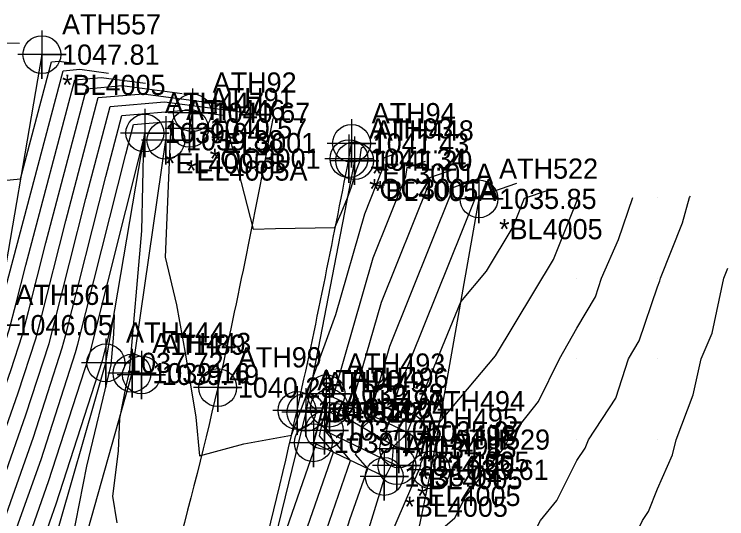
# Model space of a CAD drawing. Extents: x 1213164 to 1213550, y 766120 to 766870.
# Drawn here: x 1213390.3 to 1213478.6, y 766780.2 to 766842.7 of the extents above; entities that cross this region are included whole.
import ezdxf

# ---------------------------------------------------------------- set-up
doc = ezdxf.new("R2010")
doc.units = 0
for name, color, linetype in [('Default', 7, 'Continuous'), ('Exist DTM Breakline', 7, 'Continuous'), ('Exist DTM Breakline Cogo Comment', 7, 'Continuous'), ('Exist DTM Breakline Cogo Elevation', 7, 'Continuous'), ('Exist DTM Breakline Cogo Number', 7, 'Continuous'), ('Exist DTM Breakline Cogo Point CELL', 7, 'Continuous'), ('Exist DTM Crownline', 7, 'Continuous'), ('Exist DTM Crownline Cogo Elevation', 7, 'Continuous'), ('Exist DTM Crownline Cogo Number', 7, 'Continuous'), ('Exist DTM Crownline Cogo Point CELL', 7, 'Continuous'), ('Exist DTM QL2 LIDAR Elevation Point', 7, 'Continuous'), ('Exist Roads EOP', 7, 'Continuous'), ('Exist Roads EOP Cogo Comment', 7, 'Continuous'), ('Exist Roads EOP Cogo Elevation', 7, 'Continuous'), ('Exist Roads EOP Cogo Number', 7, 'Continuous'), ('Exist Roads EOP Cogo Point CELL', 7, 'Continuous')]:
    doc.layers.add(name, color=color, linetype=linetype)

msp = doc.modelspace()

# ---------------------------------------------------------------- linework, layer by layer
at = {"layer": 'Default'}
for points in [[(1213340, 766783.914), (1213346.197, 766783.803), (1213350, 766788.887), (1213350.252, 766789.748), (1213350.345, 766790), (1213352.211, 766797.789), (1213353.788, 766800), (1213355.691, 766804.309), (1213359.889, 766810), (1213359.934, 766810.066), (1213360, 766810.135), (1213363.986, 766816.014), (1213366.89, 766820), (1213368.115, 766821.885), (1213370, 766824.609), (1213372.455, 766827.545), (1213374.385, 766830), (1213376.747, 766833.253), (1213380, 766838.01), (1213384.981, 766839.17), (1213390.964, 766839.142)], [(1213342.135, 766770), (1213344.532, 766775.468), (1213350, 766775.398), (1213353.024, 766776.976), (1213354.408, 766780), (1213355.675, 766784.325), (1213357.755, 766790), (1213358.189, 766791.811), (1213360, 766794.351), (1213362.493, 766797.507), (1213363.789, 766800), (1213366.059, 766803.941), (1213370, 766809.883), (1213370.043, 766809.957), (1213370.062, 766810), (1213373.648, 766816.352), (1213379.123, 766820), (1213379.522, 766820.478), (1213380, 766821.085), (1213381.062, 766821.371), (1213391.073, 766822.338), (1213394.898, 766836.818), (1213395.832, 766836.898), (1213397.407, 766836.692)], [(1213389.27, 766808.897), (1213396.353, 766835.709), (1213398.446, 766835.888), (1213401.976, 766835.427)], [(1213342.06, 766740), (1213346.924, 766743.076), (1213350, 766747.184), (1213351.299, 766748.701), (1213352.342, 766750), (1213356.02, 766753.98), (1213360, 766758.382), (1213361.077, 766760), (1213363.847, 766766.153), (1213367.746, 766770), (1213368.826, 766771.174), (1213370, 766773.592), (1213377.267, 766776.571), (1213378.809, 766776.986), (1213379.962, 766782.672), (1213380.675, 766777.94), (1213388.927, 766801.313), (1213389.67, 766803.609), (1213390.551, 766806.911), (1213391.743, 766811.64), (1213397.808, 766834.6), (1213401.06, 766834.878), (1213406.544, 766834.161)], [(1213342.106, 766727.894), (1213344.486, 766730), (1213347.806, 766732.194), (1213350, 766733.538), (1213354.074, 766735.926), (1213358.171, 766740), (1213359.015, 766740.985), (1213360, 766742.211), (1213370.384, 766750.082), (1213371.539, 766754.871), (1213373.745, 766752.907), (1213380.812, 766772.675), (1213381.861, 766775.895), (1213389.865, 766798.563), (1213391.317, 766803.048), (1213392.077, 766805.896), (1213394.215, 766814.384), (1213399.263, 766833.491), (1213403.674, 766833.869), (1213411.113, 766832.895)], [(1213340, 766710.039), (1213345.861, 766714.139), (1213350, 766719.109), (1213350.563, 766720), (1213354.645, 766725.355), (1213360, 766728.235), (1213361.865, 766727.151), (1213367.981, 766729.516), (1213374.34, 766749.027), (1213374.823, 766750.271), (1213381.781, 766769.733), (1213384.002, 766776.552), (1213390.803, 766795.813), (1213392.964, 766802.487), (1213393.602, 766804.881), (1213396.688, 766817.128), (1213400.718, 766832.382), (1213406.288, 766832.859), (1213415.682, 766831.63)], [(1213342.112, 766697.888), (1213348.381, 766700), (1213349.604, 766700.396), (1213350, 766700.737), (1213351.462, 766701.499), (1213361.797, 766706.63), (1213364.872, 766714.303), (1213364.991, 766714.639), (1213366.766, 766720.251), (1213367.777, 766722.939), (1213375.885, 766747.814), (1213376.911, 766750.459), (1213382.75, 766766.792), (1213386.143, 766777.209), (1213391.741, 766793.063), (1213394.611, 766801.925), (1213395.128, 766803.866), (1213399.161, 766819.872), (1213402.173, 766831.273), (1213408.902, 766831.849), (1213420.25, 766830.364)], [(1213370.731, 766726.053), (1213377.429, 766746.602), (1213378.998, 766750.648), (1213383.718, 766763.851), (1213388.284, 766777.866), (1213392.679, 766790.313), (1213396.257, 766801.364), (1213396.654, 766802.85), (1213401.634, 766822.616), (1213403.628, 766830.164), (1213411.517, 766830.839), (1213416.18, 766830.229), (1213416.57, 766829.106), (1213419.898, 766816.103), (1213422.656, 766816.169), (1213430.019, 766816.293), (1213430.817, 766818.052), (1213431.586, 766819.952), (1213432.084, 766821.325), (1213432.692, 766823.445), (1213433.07, 766824.384), (1213433.314, 766826.182), (1213433.718, 766826.322)], [(1213390.425, 766778.523), (1213393.617, 766787.563), (1213397.904, 766800.803), (1213398.18, 766801.835), (1213404.107, 766825.36), (1213405.083, 766829.055), (1213409.963, 766829.473), (1213409.602, 766827.626), (1213409.606, 766827.357), (1213408.987, 766812.605), (1213410.391, 766806.703), (1213411.541, 766800.502), (1213412.783, 766792.805), (1213413.261, 766788.017), (1213418.736, 766789.503), (1213424.652, 766790.556), (1213425.762, 766793.537), (1213426.086, 766794.404), (1213427.001, 766796.892), (1213427.227, 766797.449), (1213430.151, 766805.518), (1213433.726, 766817.979), (1213435.948, 766823.5), (1213436.145, 766824.949), (1213437.487, 766825.415)], [(1213392.566, 766779.181), (1213394.555, 766784.814), (1213399.551, 766800.241), (1213399.705, 766800.82), (1213406.328, 766827.105), (1213406.06, 766815.865), (1213404.533, 766798.386), (1213404.112, 766796.627), (1213403.326, 766792.643), (1213403.173, 766788.574), (1213402.481, 766783.012), (1213403.013, 766779.716)], [(1213423.086, 766776.13), (1213427.725, 766789.446), (1213427.474, 766789.739), (1213427.524, 766789.959), (1213429.015, 766795.399), (1213429.815, 766795.277), (1213434.76, 766812.513), (1213438.827, 766822.617), (1213438.976, 766823.716), (1213441.257, 766824.509)], [(1213407.121, 766726.367), (1213412.78, 766738.536), (1213414.717, 766743.514), (1213414.943, 766744.295), (1213420.982, 766762.391), (1213421.345, 766763.374), (1213423.08, 766769), (1213429.851, 766788.437), (1213428.115, 766790.46), (1213428.46, 766791.982), (1213429.189, 766794.641), (1213432.107, 766794.195), (1213435.794, 766807.048), (1213441.705, 766821.733), (1213441.807, 766822.483), (1213445.026, 766823.602)], [(1213406.915, 766715.546), (1213416.344, 766739.776), (1213417.797, 766744.803), (1213422.929, 766760.184), (1213423.719, 766762.321), (1213427.493, 766774.555), (1213431.978, 766787.427), (1213428.893, 766791.02), (1213428.912, 766791.058), (1213428.916, 766791.101), (1213429.527, 766793.815), (1213429.566, 766793.852), (1213434.398, 766793.113), (1213436.828, 766801.582), (1213444.584, 766820.849), (1213444.638, 766821.25), (1213448.796, 766822.695)], [(1213417.971, 766736.038), (1213420.651, 766745.31), (1213424.877, 766757.976), (1213426.094, 766761.269), (1213431.906, 766780.109), (1213434.104, 766786.417), (1213432.592, 766788.178), (1213433.028, 766789.06), (1213433.113, 766790.061), (1213433.44, 766791.514), (1213434.358, 766792.388), (1213436.689, 766792.031), (1213437.861, 766796.117), (1213447.462, 766819.966), (1213447.469, 766820.017), (1213452.565, 766821.788)], [(1213419.598, 766732.3), (1213423.505, 766745.817), (1213426.825, 766755.768), (1213428.468, 766760.216), (1213436.144, 766785.095), (1213436.305, 766785.469), (1213436.491, 766785.74), (1213437.143, 766787.062), (1213437.31, 766789.021), (1213437.353, 766789.213), (1213438.554, 766790.355), (1213439.045, 766790.985), (1213445.628, 766807.084), (1213448.839, 766810.887), (1213452.142, 766816.379), (1213453.546, 766819.913), (1213456.335, 766820.882)], [(1213421.225, 766728.562), (1213426.358, 766746.325), (1213428.773, 766753.561), (1213430.843, 766759.163), (1213436.058, 766776.068), (1213440.351, 766786.037), (1213440.617, 766786.424), (1213440.676, 766787.084), (1213442.087, 766790.175), (1213442.282, 766790.426), (1213442.981, 766792.135), (1213449.958, 766800.396), (1213457.134, 766812.327), (1213460, 766819.541), (1213460.14, 766819.86), (1213460.187, 766820)], [(1213422.851, 766724.824), (1213429.212, 766746.832), (1213430.721, 766751.353), (1213433.217, 766758.11), (1213435.973, 766767.041), (1213439.81, 766775.952), (1213444.889, 766780.311), (1213446.229, 766782.929), (1213450, 766787.756), (1213451.006, 766788.994), (1213451.51, 766790), (1213455.256, 766794.744), (1213457.857, 766800), (1213460, 766803.813), (1213462.314, 766807.686), (1213463.093, 766810), (1213465.195, 766814.805), (1213466.976, 766820)], [(1213424.478, 766721.086), (1213432.066, 766747.34), (1213432.669, 766749.145), (1213435.592, 766757.057), (1213435.887, 766758.014), (1213436.299, 766758.97), (1213449.746, 766770.512), (1213450, 766771.007), (1213453.629, 766776.371), (1213455.504, 766780), (1213457.52, 766782.48), (1213460, 766787.434), (1213461.032, 766788.968), (1213461.443, 766790), (1213464.863, 766795.137), (1213466.403, 766800), (1213467.748, 766802.252), (1213470, 766808.933), (1213470.32, 766809.68), (1213470.389, 766810), (1213473.119, 766816.881), (1213473.967, 766820), (1213474.094, 766820.154)], [(1213432.563, 766724.347), (1213436.581, 766740.012), (1213437.508, 766743.17), (1213440, 766741.826), (1213445.936, 766744.064), (1213447.428, 766750), (1213450, 766755.519), (1213452.593, 766757.407), (1213455.201, 766760), (1213457.761, 766762.239), (1213460, 766766.007), (1213461.662, 766768.338), (1213462.651, 766770), (1213465.513, 766774.487), (1213468.136, 766780), (1213468.886, 766781.114), (1213470, 766783.912), (1213471.886, 766788.114), (1213472.323, 766790), (1213474.452, 766795.548), (1213475.417, 766800), (1213476.793, 766803.207), (1213478.245, 766810), (1213478.744, 766811.256)], [(1213379.596, 766735.396), (1213382.063, 766742.965), (1213385.261, 766751.214), (1213386.624, 766755.027), (1213394.707, 766779.838), (1213395.493, 766782.064), (1213401.198, 766799.68), (1213401.231, 766799.805), (1213402.663, 766805.491), (1213402.605, 766803.059), (1213402.275, 766799.279), (1213399.269, 766786.732), (1213397.9, 766779.789), (1213393.663, 766758.303), (1213393.59, 766756.355), (1213393.67, 766750.16), (1213393.673, 766750.105), (1213393.681, 766750.051), (1213394.967, 766742.851), (1213396.502, 766727.724)]]:
    msp.add_lwpolyline(points, dxfattribs=at)
at = {"layer": 'Exist DTM Breakline'}
for points in [[(1213393.725, 766837.712), (1213387.943, 766804.198), (1213372.969, 766750.103), (1213364.408, 766714.77), (1213354.911, 766685.163), (1213342.452, 766644.741), (1213315.98, 766668.508), (1213286.511, 766700.007), (1213270.126, 766717.647)], [(1213346.628, 766614.521), (1213356.147, 766642.326), (1213365.891, 766675.979), (1213376.506, 766712.04), (1213387.804, 766751.444), (1213401.652, 766799.525), (1213406.478, 766827.991)], [(1213348.967, 766613.21), (1213359.36, 766641.078), (1213368.166, 766674.744), (1213379.292, 766710.798), (1213391.46, 766750.473), (1213404.901, 766798.24), (1213409.089, 766827.096)], [(1213432.48, 766824.565), (1213426.442, 766793.398), (1213414.418, 766744.202), (1213402.864, 766704.233), (1213391.111, 766668.435), (1213399.916, 766666.943)], [(1213447.885, 766819.836), (1213441.941, 766786.26), (1213433.964, 766747.677), (1213424.337, 766715.269), (1213411.9, 766681.742)], [(1213436.147, 766785.447), (1213427.366, 766789.617), (1213428.949, 766795.686), (1213438.825, 766791.023)], [(1213437.948, 766788.863), (1213429.355, 766793.916), (1213428.727, 766791.148), (1213437.715, 766786.784)]]:
    msp.add_lwpolyline(points, dxfattribs=at)
at = {"layer": 'Exist DTM Breakline Cogo Point CELL'}
for points in [[(1213393.725, 766840.712), (1213393.725, 766834.712), (1213393.725, 766837.712), (1213396.725, 766837.712), (1213390.725, 766837.712)], [(1213406.478, 766830.991), (1213406.478, 766824.991), (1213406.478, 766827.991), (1213409.478, 766827.991), (1213403.478, 766827.991)], [(1213409.089, 766830.096), (1213409.089, 766824.096), (1213409.089, 766827.096), (1213412.089, 766827.096), (1213406.089, 766827.096)], [(1213432.48, 766827.565), (1213432.48, 766821.565), (1213432.48, 766824.565), (1213435.48, 766824.565), (1213429.48, 766824.565)], [(1213447.885, 766822.836), (1213447.885, 766816.836), (1213447.885, 766819.836), (1213450.885, 766819.836), (1213444.885, 766819.836)], [(1213387.943, 766807.198), (1213387.943, 766801.198), (1213387.943, 766804.198), (1213390.943, 766804.198), (1213384.943, 766804.198)], [(1213401.652, 766802.525), (1213401.652, 766796.525), (1213401.652, 766799.525), (1213404.652, 766799.525), (1213398.652, 766799.525)], [(1213404.901, 766801.24), (1213404.901, 766795.24), (1213404.901, 766798.24), (1213407.901, 766798.24), (1213401.901, 766798.24)], [(1213428.949, 766798.686), (1213428.949, 766792.686), (1213428.949, 766795.686), (1213431.949, 766795.686), (1213425.949, 766795.686)], [(1213429.355, 766796.916), (1213429.355, 766790.916), (1213429.355, 766793.916), (1213432.355, 766793.916), (1213426.355, 766793.916)], [(1213426.442, 766796.398), (1213426.442, 766790.398), (1213426.442, 766793.398), (1213429.442, 766793.398), (1213423.442, 766793.398)], [(1213428.727, 766794.148), (1213428.727, 766788.148), (1213428.727, 766791.148), (1213431.727, 766791.148), (1213425.727, 766791.148)], [(1213438.825, 766794.023), (1213438.825, 766788.023), (1213438.825, 766791.023), (1213441.825, 766791.023), (1213435.825, 766791.023)], [(1213427.366, 766792.617), (1213427.366, 766786.617), (1213427.366, 766789.617), (1213430.366, 766789.617), (1213424.366, 766789.617)], [(1213437.948, 766791.863), (1213437.948, 766785.863), (1213437.948, 766788.863), (1213440.948, 766788.863), (1213434.948, 766788.863)], [(1213437.715, 766789.784), (1213437.715, 766783.784), (1213437.715, 766786.784), (1213440.715, 766786.784), (1213434.715, 766786.784)], [(1213441.941, 766789.26), (1213441.941, 766783.26), (1213441.941, 766786.26), (1213444.941, 766786.26), (1213438.941, 766786.26)], [(1213436.147, 766788.447), (1213436.147, 766782.447), (1213436.147, 766785.447), (1213439.147, 766785.447), (1213433.147, 766785.447)]]:
    msp.add_lwpolyline(points, dxfattribs=at)
for centre in [(1213393.725, 766837.712), (1213406.478, 766827.991), (1213409.089, 766827.096), (1213432.48, 766824.565), (1213447.885, 766819.836), (1213401.652, 766799.525), (1213404.901, 766798.24), (1213428.949, 766795.686), (1213429.355, 766793.916), (1213426.442, 766793.398), (1213428.727, 766791.148), (1213438.825, 766791.023), (1213427.366, 766789.617), (1213437.948, 766788.863), (1213437.715, 766786.784), (1213441.941, 766786.26), (1213436.147, 766785.447)]:
    msp.add_circle(centre, 2.344, dxfattribs=at)
at = {"layer": 'Exist DTM Crownline'}
msp.add_spline([(1213422.346, 766829.784), (1213415.509, 766796.457), (1213402.624, 766748.087)], degree=3, dxfattribs=at)
at = {"layer": 'Exist DTM Crownline Cogo Point CELL'}
msp.add_lwpolyline([(1213415.509, 766799.457), (1213415.509, 766793.457), (1213415.509, 766796.457), (1213418.509, 766796.457), (1213412.509, 766796.457)], dxfattribs=at)
msp.add_circle((1213415.509, 766796.457), 2.344, dxfattribs=at)
at = {"layer": 'Exist DTM QL2 LIDAR Elevation Point'}
for p, q in [((1213460, 766820), (1213460, 766820)), ((1213470, 766820), (1213470, 766820)), ((1213460, 766810), (1213460, 766810)), ((1213470, 766810), (1213470, 766810)), ((1213450, 766800), (1213450, 766800)), ((1213460, 766800), (1213460, 766800)), ((1213470, 766800), (1213470, 766800)), ((1213450, 766790), (1213450, 766790)), ((1213460, 766790), (1213460, 766790)), ((1213470, 766790), (1213470, 766790))]:
    msp.add_line(p, q, dxfattribs=at)
at = {"layer": 'Exist Roads EOP'}
for p, q in [((1213412.014, 766828.572), (1213412.387, 766830.503)), ((1213431.775, 766824.817), (1213432.097, 766826.712))]:
    msp.add_line(p, q, dxfattribs=at)
msp.add_spline([(1213390.233, 766668.75), (1213399.517, 766704.888), (1213412.301, 766744.745), (1213425.35, 766793.621), (1213431.775, 766824.817)], degree=3, dxfattribs=at)
at = {"layer": 'Exist Roads EOP Cogo Point CELL'}
for points in [[(1213412.387, 766833.503), (1213412.387, 766827.503), (1213412.387, 766830.503), (1213415.387, 766830.503), (1213409.387, 766830.503)], [(1213412.014, 766831.572), (1213412.014, 766825.572), (1213412.014, 766828.572), (1213415.014, 766828.572), (1213409.014, 766828.572)], [(1213432.097, 766829.712), (1213432.097, 766823.712), (1213432.097, 766826.712), (1213435.097, 766826.712), (1213429.097, 766826.712)], [(1213431.775, 766827.817), (1213431.775, 766821.817), (1213431.775, 766824.817), (1213434.775, 766824.817), (1213428.775, 766824.817)], [(1213406.061, 766801.028), (1213406.061, 766795.028), (1213406.061, 766798.028), (1213409.061, 766798.028), (1213403.061, 766798.028)], [(1213425.35, 766796.621), (1213425.35, 766790.621), (1213425.35, 766793.621), (1213428.35, 766793.621), (1213422.35, 766793.621)]]:
    msp.add_lwpolyline(points, dxfattribs=at)
for centre in [(1213412.387, 766830.503), (1213412.014, 766828.572), (1213432.097, 766826.712), (1213431.775, 766824.817), (1213406.061, 766798.028), (1213425.35, 766793.621)]:
    msp.add_circle(centre, 2.344, dxfattribs=at)

# ---------------------------------------------------------------- texts
at = {"layer": 'Exist DTM Breakline Cogo Comment'}
for s, p in [('*BL4005', (1213396.225, 766832.712)), ('*EL4005B', (1213408.978, 766822.991)), ('*EL4005A', (1213411.589, 766822.096)), ('*BL4005A', (1213434.98, 766819.565)), ('*BL4005', (1213450.385, 766814.836)), ('*EL4005', (1213441.325, 766786.023)), ('*BL4005', (1213440.448, 766783.863)), ('*EL4005', (1213440.215, 766781.784)), ('*BL4005', (1213438.647, 766780.447))]:
    msp.add_text(s, height=2.5, dxfattribs=at).set_placement(p)
at = {"layer": 'Exist DTM Breakline Cogo Elevation'}
for s, p in [('1047.81', (1213396.225, 766836.462)), ('1039.04', (1213408.978, 766826.741)), ('1039.88', (1213411.589, 766825.846)), ('1041.20', (1213434.98, 766823.315)), ('1035.85', (1213450.385, 766818.586)), ('1046.05', (1213390.443, 766802.948)), ('1037.72', (1213404.152, 766798.275)), ('1039.16', (1213407.401, 766796.99)), ('1039.38', (1213431.449, 766794.436)), ('1037.04', (1213431.855, 766792.666)), ('1039.82', (1213428.942, 766792.148)), ('1037.05', (1213431.227, 766789.898)), ('1035.07', (1213441.325, 766789.773)), ('1039.17', (1213429.866, 766788.367)), ('1034.85', (1213440.448, 766787.613)), ('1034.86', (1213440.215, 766785.534)), ('1033.61', (1213444.441, 766785.01)), ('1035.04', (1213438.647, 766784.197))]:
    msp.add_text(s, height=2.5, dxfattribs=at).set_placement(p)
at = {"layer": 'Exist DTM Breakline Cogo Number'}
for s, p in [('ATH557', (1213396.225, 766840.212)), ('ATH447', (1213408.978, 766830.491)), ('ATH446', (1213411.589, 766829.596)), ('ATH448', (1213434.98, 766827.065)), ('ATH522', (1213450.385, 766822.336)), ('ATH561', (1213390.443, 766806.698)), ('ATH444', (1213404.152, 766802.025)), ('ATH443', (1213407.401, 766800.74)), ('ATH493', (1213431.449, 766798.186)), ('ATH496', (1213431.855, 766796.416)), ('ATH449', (1213428.942, 766795.898)), ('ATH497', (1213431.227, 766793.648)), ('ATH494', (1213441.325, 766793.523)), ('ATH492', (1213429.866, 766792.117)), ('ATH495', (1213440.448, 766791.363)), ('ATH498', (1213440.215, 766789.284)), ('ATH529', (1213444.441, 766788.76)), ('ATH491', (1213438.647, 766787.947))]:
    msp.add_text(s, height=2.5, dxfattribs=at).set_placement(p)
at = {"layer": 'Exist DTM Crownline Cogo Elevation'}
msp.add_text('1040.28', height=2.5, dxfattribs=at).set_placement((1213418.009, 766795.207))
at = {"layer": 'Exist DTM Crownline Cogo Number'}
msp.add_text('ATH99', height=2.5, dxfattribs=at).set_placement((1213418.009, 766798.957))
at = {"layer": 'Exist Roads EOP Cogo Comment'}
for s, p in [('*EL3001', (1213414.887, 766825.503)), ('*OC3001', (1213414.514, 766823.572)), ('*EL3001A', (1213434.597, 766821.712)), ('*OC3001A', (1213434.275, 766819.817))]:
    msp.add_text(s, height=2.5, dxfattribs=at).set_placement(p)
at = {"layer": 'Exist Roads EOP Cogo Elevation'}
for s, p in [('1040.67', (1213414.887, 766829.253)), ('1040.57', (1213414.514, 766827.322)), ('1041.43', (1213434.597, 766825.462)), ('1041.34', (1213434.275, 766823.567)), ('1039.49', (1213408.561, 766796.778)), ('1040.11', (1213427.85, 766792.371))]:
    msp.add_text(s, height=2.5, dxfattribs=at).set_placement(p)
at = {"layer": 'Exist Roads EOP Cogo Number'}
for s, p in [('ATH92', (1213414.887, 766833.003)), ('ATH91', (1213414.514, 766831.072)), ('ATH94', (1213434.597, 766829.212)), ('ATH93', (1213434.275, 766827.317)), ('ATH89', (1213408.561, 766800.528)), ('ATH90', (1213427.85, 766796.121))]:
    msp.add_text(s, height=2.5, dxfattribs=at).set_placement(p)

doc.saveas('drawing.dxf')
